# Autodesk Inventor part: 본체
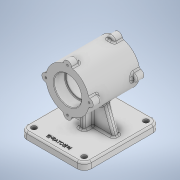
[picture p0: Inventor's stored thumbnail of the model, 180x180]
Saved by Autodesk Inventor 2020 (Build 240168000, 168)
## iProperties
Created: 2022-11
Part Number: 본체
Material: 일반
Document SubType Name: Modeling
Designer: owner
Density: 1 g/cm^3
Appearance: 기본값
Mass: 450.145 g
Surface Area: 796.917 cm^2
Volume: 450.145 cm^3
Author: owner
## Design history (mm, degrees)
sketch "스케치1"
  geometry: L1 (-55, 65)-(55, 65); L2 (55, 65)-(55, -65); L3 (55, -65)-(-55, -65); L4 (-55, -65)-(-55, 65); L5 (-55, 65)-(55, -65); L6 (55, 65)-(-55, -65); 1 further point
  constraints: 12 end point, 2 midpoint, 2 parallel, 1 horizontal, 1 perpendicular
  dimensions: "d0" = 110 distance of L2.end L3.end; "d1" = 130 distance of L1.end L2.end
extrude "돌출1" new body sketch "스케치1" distance "d2" = 12; taper "d3" = 0 deg
node "작업 평면1"
sketch "스케치2"
  geometry: L1 (0, 0)-(110, 0) reference; C1 r 37 at (55, 82); 2 further points
  constraints: 1 centre point, 1 midpoint, 1 vertical alignment
  dimensions: "d5" = 74 diameter of C1; "d6" = 82 distance from line of L1 C1.centre
extrude "돌출2" join sketch "스케치2" stored distance "d7" = 87; taper "d8" = 0 deg
sketch "스케치3"
  geometry: L1 (37, 0)-(-37, 0); L2 (0, 37)-(0, -37); C1 r 7 at (0, 37); C2 r 7 at (37, 0); C3 r 7 at (0, -37); C4 r 7 at (-37, 0); A1 r 37 centre (0, 0) between (0, 37) and (37, 0) reference; 9 further points
  constraints: 4 centre point, 4 end point, 4 point on circle, 1 horizontal, 1 horizontal alignment, 1 perpendicular, 1 vertical alignment, 2 other
  dimensions: "d9" = 14 diameter of C1; "d10" = 14 diameter of C2
extrude "돌출3" join sketch "스케치3" distance "d11" = 14; taper "d12" = 0 deg
sketch "스케치4"
  geometry: A1 r 37 centre (55, 82) between (91.338, 88.969) and (61.969, 118.338) reference; 2 further points
  constraints: 1 coincident
hole "구멍1" sketch "스케치4" at (55, 82) diameter "d13" = 42; stored, may be unused: countersink angle "d17" = 90 deg, drill point angle "d19" = 0 deg; dims "d14" = 12, "d15" = 47, "d16" = 19, "d18" = 8
sketch "스케치5"
  geometry: A1 r 37 centre (-55, 82) between (-48.031, 45.662) and (-18.662, 75.031) reference; 2 further points
  constraints: 1 coincident
hole "구멍2" sketch "스케치5" at (-55, 82) diameter "d20" = 42; stored, may be unused: countersink angle "d24" = 90 deg, drill point angle "d26" = 0 deg; dims "d21" = 12, "d22" = 47, "d23" = 19, "d25" = 8
sketch "스케치7"
  geometry: A1 r 7 centre (55, 119) between (61.969, 118.338) and (48.031, 118.338) reference; A2 r 7 centre (92, 82) between (91.338, 75.031) and (91.338, 88.969) reference; A3 r 7 centre (55, 45) between (48.031, 45.662) and (61.969, 45.662) reference; A4 r 7 centre (18, 82) between (18.662, 88.969) and (18.662, 75.031) reference; 5 further points
  constraints: 4 coincident
hole "구멍3" sketch "스케치7" at (55, 119), (92, 82), (55, 45), (18, 82) diameter "d28" = 3.242; stored, may be unused: countersink angle "d32" = 90 deg, drill point angle "d34" = 118 deg; dims "d29" = 8, "d30" = 47, "d31" = 19, "d33" = 10
sketch "스케치8"
  geometry: L1 (110, 0)-(0, 0) reference; L2 (0, 0)-(0, 12) reference; L3 (110, 12)-(0, 12) reference; L4 (110, 0)-(110, 12) reference; L5 (110, 12)-(0, 12) reference; L6 (14, 12)-(29.664, 55.036); L7 (96, 12)-(80.336, 55.036); A1 r 37 centre (55, 82) between (18.662, 75.031) and (48.031, 45.662) reference; A2 r 37 centre (55, 82) between (61.969, 45.662) and (91.338, 75.031) reference; A3 r 37 centre (55, 82) between (48.031, 45.662) and (61.969, 45.662) reference; 3 further points
  constraints: 4 end point, 2 point on circle, 2 point on line
  dimensions: "d35" = 110 deg angle of L3 L6; "d36" = 110 deg angle of L3 L7; "d37" = 14 distance of L2.end L6.start; "d38" = 14 distance of L7.start L3.start
extrude "돌출4" join sketch "스케치8" stored distance "d39" = 10; taper "d40" = 0 deg
sketch "스케치9"
  geometry: L1 (12, -65)-(12, 65) reference; L2 (12, 15)-(27.559, 15); L3 (12, 0)-(12, -10) reference; L4 (55.036, 0)-(12, 0) reference; L5 (55.036, -10)-(55.036, 0) reference; L6 (12, -10)-(55.036, -10) reference; 2 further points
  constraints: 2 end point, 1 horizontal, 1 midpoint, 1 point on line
  dimensions: "d41" = 20 distance of L2.start point (12, -5)
feature "리브1" sketch "스케치9" dims "d42" = 1, "d43" = 10, "d44" = 0, "d45" = 0, "d46" = 1, "d47" = 1
fillet "모깎기1" dims "d48" = 12
fillet "모깎기2" dims "d49" = 3
fillet "모깎기3" dims "d50" = 3
fillet "모깎기4" dims "d51" = 3
fillet "모깎기5" dims "d52" = 3
fillet "모깎기6" dims "d53" = 3
fillet "모깎기7" dims "d54" = 3
fillet "모깎기8" dims "d55" = 3
fillet "모깎기9" dims "d56" = 3
fillet "모깎기10" dims "d57" = 1
chamfer "모따기1" distance "d58" = 1; stored, may be unused: second distance "d59" = 2, angle "d60" = 45 deg
sketch "스케치10"
  geometry: A1 r 12 centre (-43, 53) between (-43, 65) and (-55, 53) reference; A2 r 12 centre (43, 53) between (55, 53) and (43, 65) reference; A3 r 12 centre (-43, -53) between (-55, -53) and (-43, -65) reference; A4 r 12 centre (43, -53) between (43, -65) and (55, -53) reference; 5 further points
  constraints: 4 coincident
hole "구멍4" sketch "스케치10" at (-43, 53), (43, 53), (-43, -53), (43, -53) diameter "d61" = 9; stored, may be unused: countersink angle "d65" = 90 deg, drill point angle "d67" = 0 deg; dims "d62" = 8, "d63" = 47, "d64" = 19, "d66" = 10
sketch "스케치11"
  geometry: L1 (77, 5)-(-77, 5) reference; L2 (43, -62)-(-43, -62) reference; 3 further points
  constraints: 1 midpoint, 1 vertical alignment, 1 other
  dimensions: "d68" = 58 distance from line of L1 point (0, -53)
feature "엠보싱1" sketch "스케치11" dims "d0" = 110, "d1" = 130, "d69" = 0.5, "d70" = 0
node "솔리드1"
mirror "미러1"
mirror "미러2"
mirror "미러3"
node "투영된 루프1"
node "투영된 루프2"
feature "A9D066F2-1C7D-4E18-AEED-F7BC21143FA4" dims "d13" = 42, "d14" = 12, "d15" = 47, "d16" = 19, "d17" = 90 deg, "d18" = 8, "d19" = 0
